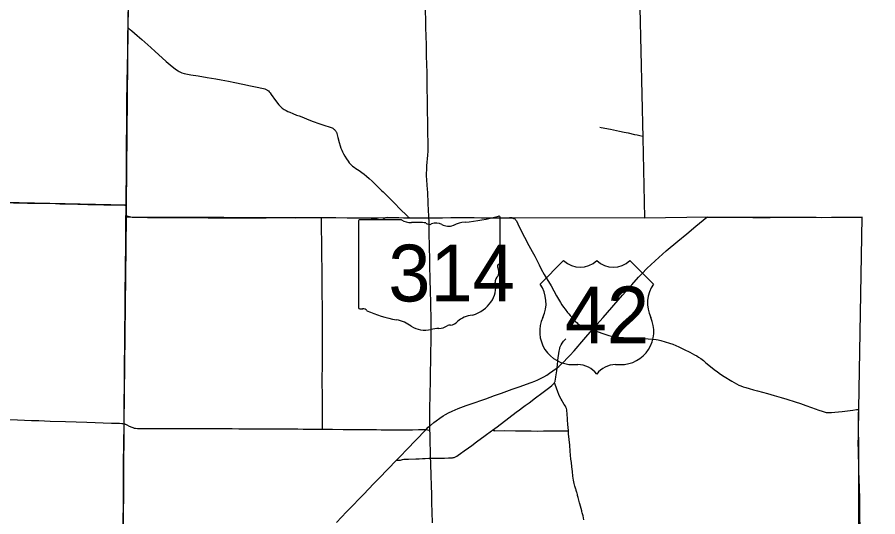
# Model space of a CAD drawing. Extents: x 9078 to 9739, y 4248 to 4966.
# Drawn here: x 9565.4 to 9671, y 4766.6 to 4827.9 of the extents above; entities that cross this region are included whole.
import ezdxf

# ---------------------------------------------------------------- set-up
doc = ezdxf.new("R2010")
doc.units = 0
for name, color, linetype in [('GM_X_County', 7, 'Continuous'), ('GM_X_County_Road', 7, 'Continuous'), ('GM_X_State_Route', 7, 'Continuous'), ('GM_X_State_Shield', 7, 'Continuous'), ('GM_X_Township', 7, 'Continuous'), ('GM_X_Township_Road', 7, 'Continuous'), ('GM_X_US_Route', 7, 'Continuous'), ('GM_X_US_Shield', 7, 'Continuous')]:
    doc.layers.add(name, color=color, linetype=linetype)

msp = doc.modelspace()

# ---------------------------------------------------------------- linework, layer by layer
at = {"layer": 'GM_X_County'}
msp.add_lwpolyline([(9641.78, 4828.99), (9642.12, 4813.07), (9642.33, 4803.27), (9650.1, 4803.37), (9669.01, 4803.28), (9668.62, 4779.81), (9668.56, 4779.06), (9668.59, 4773.73), (9668.6, 4765.27), (9669.18, 4750.13), (9669.69, 4737.44), (9670.24, 4714.5), (9670.33, 4710.79), (9670.98, 4684.3)], dxfattribs=at)
at = {"layer": 'GM_X_County_Road'}
for points in [[(9634.53, 4790.04), (9634.86, 4789.89), (9635.13, 4789.78), (9635.49, 4789.66), (9635.82, 4789.55), (9635.94, 4789.51)], [(9635.94, 4789.51), (9636.11, 4789.46), (9636.34, 4789.38), (9637.12, 4789.12), (9637.58, 4788.96), (9637.98, 4788.84), (9638.3, 4788.76), (9638.54, 4788.71), (9638.86, 4788.66), (9639.19, 4788.62), (9639.76, 4788.58), (9641.1, 4788.51), (9642.8, 4788.43), (9643.37, 4788.38), (9643.77, 4788.32), (9644.01, 4788.28), (9644.33, 4788.21), (9644.88, 4788.05), (9645.43, 4787.88), (9645.82, 4787.74), (9646.2, 4787.59), (9646.57, 4787.42), (9647.23, 4787.1), (9647.89, 4786.76), (9648.48, 4786.47), (9648.76, 4786.31), (9648.97, 4786.18), (9649.24, 4786), (9649.57, 4785.75), (9649.89, 4785.49), (9650.45, 4785.02), (9650.9, 4784.67), (9651.29, 4784.37), (9651.69, 4784.08), (9652.11, 4783.81), (9653.08, 4783.21), (9653.35, 4783.05), (9653.63, 4782.9), (9653.93, 4782.75), (9654.15, 4782.65), (9654.46, 4782.54), (9654.78, 4782.43), (9655.2, 4782.31), (9655.73, 4782.17), (9656.21, 4782.03), (9657.45, 4781.69), (9658.24, 4781.47), (9659.1, 4781.21), (9659.8, 4781.01), (9660.82, 4780.69), (9661.49, 4780.47), (9662.15, 4780.24), (9662.84, 4779.99), (9663.76, 4779.65), (9664.13, 4779.53), (9664.4, 4779.45), (9664.53, 4779.42), (9664.65, 4779.39), (9664.82, 4779.37), (9665.05, 4779.36), (9665.3, 4779.37), (9665.72, 4779.41), (9666.6, 4779.52), (9667.91, 4779.68), (9668.38, 4779.74), (9668.66, 4779.75)], [(9631.62, 4784.86), (9631.63, 4784.98), (9631.65, 4785.14), (9631.72, 4785.78), (9631.88, 4786.89), (9631.94, 4787.21), (9631.95, 4787.29), (9631.97, 4787.37), (9632, 4787.44), (9632.07, 4787.59), (9632.11, 4787.66), (9632.23, 4787.87), (9632.32, 4788), (9632.42, 4788.13), (9632.58, 4788.31), (9632.63, 4788.37), (9632.68, 4788.43)], [(9631.28, 4783.03), (9631.29, 4783.05), (9631.33, 4783.12), (9631.36, 4783.19), (9631.39, 4783.27), (9631.43, 4783.42), (9631.48, 4783.74), (9631.57, 4784.48), (9631.62, 4784.86)], [(9623.69, 4777.23), (9624.24, 4777.64), (9625.68, 4778.72), (9626.6, 4779.4), (9626.99, 4779.7), (9627.38, 4780), (9627.71, 4780.25), (9628.17, 4780.58), (9628.96, 4781.17), (9629.75, 4781.75), (9630.4, 4782.24), (9630.72, 4782.49), (9630.97, 4782.7), (9631.1, 4782.8), (9631.15, 4782.86), (9631.2, 4782.92), (9631.25, 4782.98), (9631.28, 4783.03)], [(9552.31, 4778.95), (9552.42, 4778.95), (9554.63, 4778.87), (9560.61, 4778.63), (9561.68, 4778.59), (9565.37, 4778.46), (9567.09, 4778.4), (9567.99, 4778.38), (9569.38, 4778.33), (9571.27, 4778.27), (9573.89, 4778.19), (9576.92, 4778.09), (9577.91, 4778.06), (9578.2, 4778.04), (9578.33, 4778.02), (9578.46, 4777.99)], [(9578.35, 4764.83), (9578.35, 4764.92), (9578.35, 4765.49), (9578.37, 4766.56), (9578.38, 4767.63), (9578.38, 4768.78), (9578.41, 4771.07), (9578.41, 4772.06), (9578.41, 4772.88), (9578.41, 4773.54), (9578.43, 4775.18), (9578.45, 4776.33), (9578.46, 4777.15), (9578.46, 4777.76), (9578.46, 4777.99)], [(9578.46, 4777.99), (9578.56, 4777.97), (9578.62, 4777.95), (9578.72, 4777.91), (9578.8, 4777.87), (9579.1, 4777.72), (9579.4, 4777.58), (9579.55, 4777.52), (9579.71, 4777.47), (9579.87, 4777.44), (9580.11, 4777.42), (9580.36, 4777.41), (9581.26, 4777.4), (9582.32, 4777.4), (9586.99, 4777.41), (9591.01, 4777.4), (9591.75, 4777.4), (9592.57, 4777.39), (9593.3, 4777.39), (9593.8, 4777.38), (9594.37, 4777.38), (9595.02, 4777.39), (9596.34, 4777.38), (9597.16, 4777.37), (9597.98, 4777.36), (9598.55, 4777.36), (9598.96, 4777.36), (9599.78, 4777.36), (9600.43, 4777.35), (9601.5, 4777.34), (9601.99, 4777.34), (9602.72, 4777.33), (9602.83, 4777.33)], [(9602.83, 4777.33), (9603.21, 4777.33), (9604.03, 4777.32), (9605.35, 4777.31), (9606.16, 4777.31), (9607.03, 4777.3)], [(9607.03, 4777.3), (9607.07, 4777.3), (9607.72, 4777.29), (9608.46, 4777.29), (9609.44, 4777.28), (9610.02, 4777.27), (9610.59, 4777.27), (9611.41, 4777.27), (9611.9, 4777.27), (9612.8, 4777.27), (9613.37, 4777.26), (9613.86, 4777.26), (9614.61, 4777.28), (9614.97, 4777.28), (9615.54, 4777.3)], [(9615.54, 4777.3), (9615.71, 4777.27), (9615.89, 4777.22), (9616.01, 4777.18)], [(9616.09, 4773.78), (9616.89, 4773.77), (9617.38, 4773.79), (9617.78, 4773.79), (9618.27, 4773.8), (9618.6, 4773.81), (9618.76, 4773.82), (9618.84, 4773.84), (9618.92, 4773.85), (9619, 4773.87), (9619.07, 4773.9), (9619.15, 4773.93), (9619.29, 4774.01), (9619.49, 4774.14), (9619.75, 4774.34), (9620.22, 4774.67), (9620.75, 4775.05), (9621.15, 4775.34), (9621.74, 4775.78), (9622.79, 4776.56), (9623.58, 4777.14), (9623.69, 4777.23)], [(9611.9, 4773.53), (9612.13, 4773.53), (9612.4, 4773.55), (9612.64, 4773.6), (9612.82, 4773.64), (9613.06, 4773.65), (9613.38, 4773.67), (9614.27, 4773.69), (9614.68, 4773.7), (9615.1, 4773.73), (9615.42, 4773.75), (9615.89, 4773.78), (9616.09, 4773.78)]]:
    msp.add_lwpolyline(points, dxfattribs=at)
at = {"layer": 'GM_X_State_Route'}
for points in [[(9615.99, 4777.74), (9615.99, 4777.87), (9615.99, 4778.04), (9615.99, 4778.53), (9616, 4779.1), (9616, 4779.59), (9616.01, 4780), (9616.04, 4781.39), (9616.05, 4782.13), (9616.07, 4782.79), (9616.08, 4783.94), (9616.09, 4784.6), (9616.11, 4785.42), (9616.13, 4786.98), (9616.14, 4787.88), (9616.15, 4789.52), (9616.15, 4790.67), (9616.14, 4791.33), (9616.13, 4792.15), (9616.1, 4793.21), (9616.08, 4793.95), (9616.07, 4794.44), (9616.05, 4795.51), (9616.01, 4797.56), (9615.98, 4798.55), (9615.96, 4799.29), (9615.95, 4799.7), (9615.92, 4801.42), (9615.91, 4802.24), (9615.9, 4802.9), (9615.87, 4803.26), (9615.86, 4803.48), (9615.84, 4804.14), (9615.81, 4805.04), (9615.79, 4805.53), (9615.77, 4805.86), (9615.74, 4806.35), (9615.71, 4806.76), (9615.68, 4807.25), (9615.63, 4807.9), (9615.6, 4808.39), (9615.6, 4808.72), (9615.61, 4809.13), (9615.64, 4809.62), (9615.76, 4810.92), (9615.79, 4811.42), (9615.8, 4811.91), (9615.79, 4812.57), (9615.77, 4813.55), (9615.76, 4814.04), (9615.74, 4815.11), (9615.71, 4816.26), (9615.7, 4816.99), (9615.7, 4817.73), (9615.67, 4819.13), (9615.65, 4820.28), (9615.65, 4820.77), (9615.61, 4822.33), (9615.6, 4822.82), (9615.58, 4823.72), (9615.57, 4824.46), (9615.53, 4825.52), (9615.51, 4826.59), (9615.49, 4827.25), (9615.45, 4828.89)], [(9616.27, 4767.48), (9616.26, 4767.99), (9616.23, 4769.22), (9616.19, 4770.53), (9616.16, 4771.51), (9616.14, 4772.17), (9616.13, 4772.57), (9616.11, 4773.39), (9616.09, 4773.72), (9616.09, 4773.78), (9616.08, 4774.12), (9616.06, 4774.86), (9616.04, 4775.51), (9616.03, 4775.98), (9616.03, 4776.24), (9616.03, 4776.41), (9616.02, 4776.8), (9616.01, 4777.18), (9616, 4777.3), (9616, 4777.63), (9615.99, 4777.74)], [(9616.31, 4765.85), (9616.28, 4767.17), (9616.27, 4767.48)]]:
    msp.add_lwpolyline(points, dxfattribs=at)
at = {"layer": 'GM_X_State_Shield'}
for p, q in [((9607.23, 4802.83), (9607.23, 4792.26)), ((9612.5, 4803.01), (9607.41, 4803.01)), ((9624.64, 4797.74), (9624.64, 4803.27)), ((9624.63, 4797.74), (9624.64, 4797.74))]:
    msp.add_line(p, q, dxfattribs=at)
for centre, major_axis, start_param, end_param in [((9607.43, 4802.85), (0.202, 0), 1.712693, 3.28349), ((9613.72, 4804.23), (1.96, 0), 4.042523, 4.731795), ((9618.44, 4817.41), (18.45, 0), 4.814394, 5.042369), ((9624.44, 4803.29), (0.194, 0), 6.141152, 7.989035), ((9614.36, 4797.08), (7.02, 0), 1.404758, 1.657858), ((9615.96, 4802.9), (0.564, 0), 3.836095, 5.185415), ((9616.79, 4801.68), (1.17, 0), 0.950623, 2.079405), ((9618.3, 4803.36), (1.41, 0), 4.081561, 5.145723), ((9620.79, 4799.78), (3.71, 0), 1.699011, 2.107814), ((9624.59, 4797.34), (0.3, 0), 1.883978, 3.671073), ((9624.43, 4797.72), (0.207, 0), 5.05454, 6.418171), ((9622.68, 4796.64), (1.8, 0), 5.934695, 6.695948), ((9625.33, 4795.43), (1.31, 0), 2.387724, 3.262537), ((9619.47, 4794.73), (4.62, 0), 5.101752, 6.440018), ((9607.44, 4792.24), (0.203, 0), 3.00124, 4.508301), ((9607.47, 4793.32), (1.55, 0), 4.665946, 4.897461), ((9607.78, 4791.65), (0.56, 0), 0.519207, 1.627899), ((9614.85, 4801.14), (13.33, 0), 4.195997, 4.488961), ((9621.42, 4789.29), (2.53, 0), 1.647645, 2.488434), ((9610.88, 4787.51), (4.17, 0), 0.823519, 1.323587), ((9618.21, 4791.24), (1.49, 0), 4.937069, 5.64225), ((9615.39, 4791.6), (2.65, 0), 4.026481, 4.996735), ((9616.92, 4787.94), (2.17, 0), 1.495662, 1.94098), ((9617.11, 4790.81), (1.41, 0), 4.691044, 5.507374), ((9618.38, 4789.78), (0.397, 0), 1.147584, 2.315152)]:
    msp.add_ellipse(centre, major_axis=major_axis, ratio=0.8, start_param=start_param, end_param=end_param, dxfattribs=at)
at = {"layer": 'GM_X_Township'}
for points in [[(9580.15, 4937.8), (9580.15, 4936.95), (9580.08, 4917.87), (9580.06, 4916.03), (9579.84, 4897.51), (9579.77, 4888.99), (9579.65, 4884.67), (9579.69, 4884.1), (9579.47, 4870.94), (9579.37, 4860.56), (9579.29, 4851.87), (9579.08, 4834.3), (9579.03, 4831.16), (9578.94, 4826.71), (9578.72, 4804.83)], [(9447.11, 4807.68), (9473.64, 4807.27), (9473.65, 4807.2), (9474.08, 4807.25), (9499.81, 4806.88), (9539.23, 4805.79), (9552.42, 4805.41), (9578.72, 4804.83), (9578.72, 4803.36), (9578.45, 4777.99), (9578.35, 4764.86), (9578.2, 4742.45), (9578.15, 4739.34), (9578.12, 4738.05), (9577.81, 4724.91), (9577.47, 4698.37)], [(9578.72, 4803.36), (9578.72, 4804.83)], [(9578.72, 4803.36), (9602.71, 4803.31), (9608.69, 4803.26), (9610.62, 4803.31), (9610.82, 4803.34), (9613.6, 4803.26), (9615.9, 4803.26), (9625.77, 4803.31), (9626.12, 4803.28), (9642.33, 4803.27), (9650.1, 4803.37), (9669.01, 4803.28)]]:
    msp.add_lwpolyline(points, dxfattribs=at)
at = {"layer": 'GM_X_Township_Road'}
for points in [[(9578.95, 4826.54), (9578.95, 4826.56), (9578.97, 4827.71), (9578.98, 4828.04), (9578.98, 4828.36), (9578.99, 4828.77), (9579.01, 4829.84), (9579.03, 4830.66), (9579.03, 4831.11)], [(9578.72, 4804.8), (9578.72, 4804.93), (9578.72, 4805.42), (9578.72, 4805.75), (9578.73, 4806.49), (9578.74, 4806.9), (9578.75, 4807.64), (9578.76, 4808.54), (9578.77, 4809.69), (9578.77, 4810.18), (9578.77, 4810.67), (9578.78, 4811.24), (9578.78, 4812.39), (9578.78, 4812.96), (9578.79, 4813.94), (9578.8, 4814.85), (9578.8, 4816.24), (9578.8, 4816.57), (9578.81, 4817.14), (9578.82, 4817.39), (9578.82, 4817.8), (9578.85, 4819.51), (9578.86, 4820.01), (9578.89, 4821.64), (9578.9, 4822.21), (9578.91, 4823.16), (9578.93, 4824.02), (9578.92, 4824.76), (9578.93, 4825.58), (9578.94, 4825.99), (9578.95, 4826.54)], [(9578.95, 4826.54), (9579.14, 4826.4), (9579.21, 4826.35), (9579.4, 4826.19), (9580.09, 4825.61), (9580.64, 4825.12), (9581.39, 4824.48), (9581.76, 4824.15), (9582.29, 4823.65), (9583.14, 4822.87), (9583.62, 4822.43), (9583.87, 4822.21), (9584.12, 4822), (9584.57, 4821.64), (9584.89, 4821.39), (9585.1, 4821.26), (9585.24, 4821.18), (9585.39, 4821.11), (9585.54, 4821.05), (9585.86, 4820.97), (9586.26, 4820.87), (9586.66, 4820.79), (9587.55, 4820.65), (9588.68, 4820.47), (9589.74, 4820.29), (9590.38, 4820.18), (9591.27, 4820), (9592.07, 4819.83), (9593.03, 4819.63), (9593.99, 4819.43), (9594.39, 4819.35), (9594.8, 4819.28), (9595.36, 4819.17), (9595.6, 4819.11), (9595.76, 4819.06), (9595.91, 4819), (9595.98, 4818.96), (9596.05, 4818.92), (9596.11, 4818.87), (9596.18, 4818.81), (9596.29, 4818.69), (9596.39, 4818.57), (9596.54, 4818.37), (9597.07, 4817.64), (9597.47, 4817.12), (9597.63, 4816.93), (9597.74, 4816.81), (9597.86, 4816.7), (9597.99, 4816.61), (9598.13, 4816.52), (9598.35, 4816.4), (9598.57, 4816.3), (9598.8, 4816.2), (9599.18, 4816.05), (9599.63, 4815.86), (9599.94, 4815.75), (9600.47, 4815.54), (9600.93, 4815.36), (9601.69, 4815.06), (9602.39, 4814.82), (9603.09, 4814.59), (9603.64, 4814.42), (9603.87, 4814.34), (9604.02, 4814.27), (9604.09, 4814.23), (9604.16, 4814.18), (9604.22, 4814.13), (9604.28, 4814.08), (9604.34, 4814.01), (9604.39, 4813.95), (9604.44, 4813.88), (9604.48, 4813.81), (9604.52, 4813.74), (9604.58, 4813.59), (9604.63, 4813.43), (9604.71, 4813.12), (9604.87, 4812.48), (9604.99, 4812.09), (9605.09, 4811.78), (9605.18, 4811.55), (9605.28, 4811.33), (9605.4, 4811.11), (9605.56, 4810.82), (9605.78, 4810.48), (9605.96, 4810.21), (9606.11, 4810.01), (9606.27, 4809.83), (9606.39, 4809.71), (9606.51, 4809.6), (9606.71, 4809.45), (9606.91, 4809.32), (9607.32, 4809.05), (9607.66, 4808.82), (9607.92, 4808.62), (9608.24, 4808.36), (9608.55, 4808.09), (9608.9, 4807.75), (9609.31, 4807.35), (9609.67, 4807.01), (9610.07, 4806.61), (9610.25, 4806.44), (9610.67, 4806.05), (9610.85, 4805.87), (9611.42, 4805.3), (9611.59, 4805.12), (9612.45, 4804.24), (9613.09, 4803.6), (9613.24, 4803.45), (9613.31, 4803.39), (9613.37, 4803.34), (9613.44, 4803.3), (9613.51, 4803.26)], [(9636.88, 4814.36), (9637.04, 4814.33), (9638.16, 4814.11), (9639.28, 4813.88), (9639.84, 4813.76), (9640.32, 4813.66), (9641.11, 4813.48), (9641.43, 4813.41), (9641.75, 4813.35), (9642.14, 4813.26)], [(9552.45, 4805.41), (9553.43, 4805.37), (9555.48, 4805.32), (9556.95, 4805.27), (9557.61, 4805.26), (9558.1, 4805.25), (9558.76, 4805.24), (9559.17, 4805.23), (9560.89, 4805.19), (9563.02, 4805.15), (9564.91, 4805.09), (9565.7, 4805.08)], [(9565.7, 4805.08), (9566.62, 4805.07), (9567.72, 4805.05), (9570.07, 4804.99), (9570.57, 4804.98), (9571.47, 4804.95), (9572.78, 4804.93), (9574.01, 4804.9), (9575.08, 4804.87), (9575.98, 4804.85), (9577.05, 4804.84), (9577.7, 4804.83), (9578.57, 4804.81), (9578.72, 4804.8)], [(9578.72, 4804.8), (9578.71, 4804.28), (9578.71, 4803.79), (9578.7, 4803.53)], [(9578.59, 4790.92), (9578.59, 4791.66), (9578.6, 4792.4), (9578.59, 4793.05), (9578.6, 4793.63), (9578.61, 4794.36), (9578.62, 4795.02), (9578.63, 4795.76), (9578.64, 4796.74), (9578.64, 4797.15), (9578.65, 4797.81), (9578.67, 4799.36), (9578.68, 4800.02), (9578.68, 4800.92), (9578.69, 4801.82), (9578.69, 4802.39), (9578.7, 4802.89), (9578.7, 4803.53)], [(9578.7, 4803.53), (9578.79, 4803.51), (9579.12, 4803.41), (9579.28, 4803.37), (9579.44, 4803.35), (9579.69, 4803.34), (9580.18, 4803.32), (9581.33, 4803.3), (9582.32, 4803.29), (9584.03, 4803.29), (9584.69, 4803.29), (9585.26, 4803.29), (9586.5, 4803.28), (9587.56, 4803.28), (9588.8, 4803.27), (9590.27, 4803.25), (9591.09, 4803.26), (9591.75, 4803.27), (9592.4, 4803.26), (9593.3, 4803.26), (9594.02, 4803.26), (9594.62, 4803.26), (9595.28, 4803.26), (9595.92, 4803.27), (9596.82, 4803.29), (9597.9, 4803.29), (9598.72, 4803.28), (9599.54, 4803.27), (9600.42, 4803.29), (9601.59, 4803.28), (9602.57, 4803.29), (9602.7, 4803.29)], [(9602.7, 4803.29), (9602.98, 4803.29), (9603.71, 4803.28), (9604.45, 4803.28), (9605.83, 4803.26), (9606.74, 4803.26), (9607.29, 4803.26), (9608.21, 4803.24), (9608.8, 4803.23), (9609.05, 4803.22), (9609.13, 4803.21)], [(9602.79, 4795.51), (9602.78, 4795.82), (9602.77, 4796.47), (9602.76, 4797.37), (9602.75, 4798.19), (9602.72, 4799.5), (9602.72, 4800.4), (9602.7, 4801.79), (9602.7, 4802.53), (9602.7, 4803.02), (9602.7, 4803.19), (9602.7, 4803.29)], [(9609.13, 4803.21), (9609.21, 4803.2), (9609.37, 4803.17), (9609.69, 4803.08), (9609.85, 4803.05), (9609.93, 4803.04), (9610.01, 4803.03), (9610.09, 4803.04), (9610.17, 4803.05), (9610.25, 4803.09), (9610.38, 4803.17), (9610.45, 4803.21)], [(9610.45, 4803.21), (9610.52, 4803.25), (9610.59, 4803.28), (9610.66, 4803.3), (9610.76, 4803.3), (9610.88, 4803.3), (9611.11, 4803.3), (9611.76, 4803.28), (9612.75, 4803.27), (9613.51, 4803.26)], [(9613.51, 4803.26), (9613.9, 4803.26), (9615.03, 4803.26), (9615.77, 4803.26), (9615.87, 4803.26)], [(9615.87, 4803.26), (9616.52, 4803.27), (9617.55, 4803.27), (9618.56, 4803.28), (9619.63, 4803.3), (9620.17, 4803.29), (9620.98, 4803.28), (9621.43, 4803.28), (9622.33, 4803.26), (9622.99, 4803.26), (9623.89, 4803.26), (9624.64, 4803.27), (9625.29, 4803.26), (9625.86, 4803.25), (9625.97, 4803.24)], [(9625.97, 4803.24), (9626.03, 4803.24), (9626.19, 4803.21), (9626.27, 4803.19), (9626.34, 4803.16), (9626.42, 4803.13), (9626.48, 4803.07), (9626.53, 4803.01), (9626.62, 4802.87), (9626.8, 4802.5), (9627.02, 4802.06), (9627.62, 4800.9), (9628.15, 4799.87), (9628.57, 4799.11), (9628.88, 4798.54), (9629.41, 4797.49), (9629.67, 4796.97), (9630.04, 4796.32), (9630.29, 4795.91), (9630.56, 4795.46), (9630.87, 4794.93), (9631.23, 4794.28), (9631.56, 4793.7), (9632.04, 4792.86), (9632.21, 4792.58), (9632.4, 4792.3), (9632.6, 4792.04), (9632.91, 4791.66), (9633.07, 4791.48), (9633.23, 4791.29), (9633.55, 4790.91), (9633.88, 4790.54), (9634.06, 4790.37), (9634.17, 4790.27), (9634.3, 4790.17), (9634.53, 4790.04)], [(9650.01, 4803.35), (9650.45, 4803.33), (9650.78, 4803.32), (9651.03, 4803.32), (9651.36, 4803.32), (9651.85, 4803.32), (9652.09, 4803.33), (9652.5, 4803.33), (9652.75, 4803.33), (9653.32, 4803.33), (9653.57, 4803.32), (9653.98, 4803.32), (9654.55, 4803.32), (9655.12, 4803.32), (9655.62, 4803.31), (9656.19, 4803.31), (9656.85, 4803.31), (9657.75, 4803.31), (9658.24, 4803.32), (9659.14, 4803.33), (9659.64, 4803.33), (9660.29, 4803.33), (9660.62, 4803.32), (9661.03, 4803.32), (9661.36, 4803.32), (9661.69, 4803.32), (9662.26, 4803.32), (9662.75, 4803.32), (9663.41, 4803.32), (9664.07, 4803.31), (9665.3, 4803.32), (9666.2, 4803.33), (9666.69, 4803.33), (9667.59, 4803.34), (9668.41, 4803.34), (9669.11, 4803.34)], [(9602.83, 4786.36), (9602.83, 4786.57), (9602.84, 4787.06), (9602.84, 4788.2), (9602.84, 4788.61), (9602.84, 4789.18), (9602.83, 4790.41), (9602.82, 4791.23), (9602.82, 4792.21), (9602.81, 4792.87), (9602.8, 4793.44), (9602.8, 4794.01), (9602.8, 4794.67), (9602.79, 4795.32), (9602.79, 4795.51)], [(9578.46, 4777.99), (9578.46, 4778.26), (9578.47, 4778.7), (9578.47, 4779.28), (9578.47, 4780.34), (9578.48, 4781), (9578.5, 4782.31), (9578.51, 4783.62), (9578.52, 4785.02), (9578.52, 4785.84), (9578.54, 4787.06), (9578.55, 4787.97), (9578.56, 4788.95), (9578.58, 4789.69), (9578.58, 4790.35), (9578.59, 4790.92)], [(9602.83, 4779.97), (9602.83, 4780.43), (9602.81, 4781.5), (9602.81, 4781.99), (9602.8, 4782.56), (9602.8, 4783.29), (9602.8, 4784.03), (9602.81, 4784.6), (9602.82, 4785.58), (9602.83, 4785.99), (9602.83, 4786.36)], [(9633, 4777.13), (9633, 4777.18), (9632.95, 4777.92), (9632.91, 4778.49), (9632.85, 4779.31), (9632.82, 4779.55), (9632.79, 4779.71), (9632.75, 4779.87), (9632.69, 4780.02), (9632.63, 4780.16), (9632.5, 4780.37), (9632.33, 4780.65), (9632.24, 4780.79), (9632.12, 4781), (9631.97, 4781.3), (9631.83, 4781.6), (9631.72, 4781.91), (9631.56, 4782.38), (9631.38, 4782.83), (9631.28, 4783.03)], [(9602.83, 4777.33), (9602.83, 4777.49), (9602.83, 4778.55), (9602.83, 4779.12), (9602.83, 4779.97)], [(9668.65, 4779.04), (9668.66, 4779.41), (9668.66, 4779.75)], [(9668.8, 4765.49), (9668.79, 4766.44), (9668.78, 4767.01), (9668.77, 4767.91), (9668.77, 4768.32), (9668.76, 4768.81), (9668.72, 4770.2), (9668.7, 4771.11), (9668.67, 4772.25), (9668.65, 4773.07), (9668.62, 4774.14), (9668.6, 4774.55), (9668.59, 4774.86), (9668.58, 4775.53), (9668.58, 4775.86), (9668.59, 4776.18), (9668.6, 4777.17), (9668.62, 4777.91), (9668.64, 4778.81), (9668.65, 4779.04)], [(9623.69, 4777.23), (9623.83, 4777.18), (9623.9, 4777.16), (9623.94, 4777.16), (9623.97, 4777.15), (9625.2, 4777.16), (9626.53, 4777.15), (9628.44, 4777.13), (9629.21, 4777.11), (9629.93, 4777.12), (9631, 4777.12), (9631.84, 4777.13), (9632.85, 4777.13), (9633, 4777.13)], [(9634.91, 4766.22), (9634.8, 4766.69), (9634.7, 4767.08), (9634.65, 4767.23), (9634.64, 4767.31), (9634.56, 4767.62), (9634.42, 4768.17), (9634.38, 4768.32), (9634.32, 4768.48), (9634.25, 4768.79), (9634.2, 4768.95), (9634.14, 4769.18), (9634.1, 4769.34), (9634.06, 4769.49), (9634.03, 4769.57), (9633.97, 4769.8), (9633.94, 4769.88), (9633.91, 4769.96), (9633.79, 4770.35), (9633.71, 4770.67), (9633.63, 4771.07), (9633.56, 4771.56), (9633.49, 4772.13), (9633.43, 4772.7), (9633.37, 4773.26), (9633.32, 4773.67), (9633.22, 4774.65), (9633.17, 4775.39), (9633.03, 4776.77), (9633, 4777.13)]]:
    msp.add_lwpolyline(points, dxfattribs=at)
at = {"layer": 'GM_X_US_Route'}
for points in [[(9620.46, 4780.22), (9620.93, 4780.4), (9622.87, 4781.07), (9623.95, 4781.46), (9624.8, 4781.76), (9626.11, 4782.22), (9626.96, 4782.53), (9628.43, 4783.05), (9628.89, 4783.23), (9629.27, 4783.39), (9629.64, 4783.57), (9630, 4783.76), (9630.36, 4783.97), (9630.7, 4784.19), (9631.11, 4784.47), (9631.51, 4784.76), (9631.62, 4784.86), (9631.82, 4785.02), (9632.13, 4785.3), (9632.49, 4785.64), (9632.83, 4785.99), (9633.17, 4786.35), (9633.71, 4786.96), (9634.9, 4788.32), (9635.94, 4789.51), (9636.14, 4789.75), (9637.28, 4791.04), (9639.66, 4793.75), (9640.41, 4794.62), (9640.79, 4795.05), (9641.61, 4795.97), (9642.01, 4796.38), (9642.69, 4797.09), (9643.1, 4797.49), (9643.64, 4797.99), (9644.55, 4798.81), (9644.99, 4799.19), (9646.44, 4800.39), (9647.52, 4801.27), (9648.66, 4802.21), (9650.01, 4803.35)], [(9607.16, 4768.63), (9607.31, 4768.79), (9607.88, 4769.38), (9608.46, 4769.96), (9609.14, 4770.67), (9609.78, 4771.32), (9610.85, 4772.44), (9611.9, 4773.53), (9612.39, 4774.04), (9613.19, 4774.86), (9615.47, 4777.23), (9615.54, 4777.3), (9615.81, 4777.57), (9615.99, 4777.74), (9616.06, 4777.79), (9616.5, 4778.16), (9616.76, 4778.36), (9617.22, 4778.69), (9617.63, 4778.96), (9617.91, 4779.13), (9618.27, 4779.32), (9618.72, 4779.54), (9619.09, 4779.71), (9619.47, 4779.86), (9620.46, 4780.22)], [(9604.53, 4765.89), (9605.78, 4767.19), (9606.69, 4768.14), (9607.16, 4768.63)]]:
    msp.add_lwpolyline(points, dxfattribs=at)
at = {"layer": 'GM_X_US_Shield'}
for p, q in [((9632.42, 4798.02), (9629.52, 4795.12)), ((9643.44, 4795.12), (9640.54, 4798.02)), ((9633.58, 4785.25), (9634.16, 4785.25)), ((9638.8, 4785.25), (9639.38, 4785.25))]:
    msp.add_line(p, q, dxfattribs=at)
for centre, radius, start, end in [((9634.45, 4800.09), 2.9, 225.573, 314.427), ((9638.51, 4800.09), 2.9, 225.573, 314.427), ((9626.2, 4792.79), 4.06, 334.5471, 35.0009), ((9646.77, 4792.79), 4.06, 144.9991, 205.4529), ((9633.54, 4789.31), 4.06, 154.8319, 270.6383), ((9639.43, 4789.31), 4.06, 269.3617, 25.1681), ((9634.16, 4782.35), 2.9, 36.8699, 90), ((9638.8, 4782.35), 2.9, 90, 143.1301)]:
    msp.add_arc(centre, radius, start, end, dxfattribs=at)

# ---------------------------------------------------------------- texts
at = {"layer": 'GM_X_State_Shield'}
msp.add_text('314', height=6.961, dxfattribs=at).set_placement((9610.9, 4793))
at = {"layer": 'GM_X_US_Shield'}
msp.add_text('42', height=6.961, dxfattribs=at).set_placement((9632.56, 4787.86))

doc.saveas('drawing.dxf')
